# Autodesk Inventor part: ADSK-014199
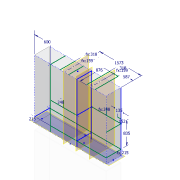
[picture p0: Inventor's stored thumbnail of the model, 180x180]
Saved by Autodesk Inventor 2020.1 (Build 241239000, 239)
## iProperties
Created: 2019-10
Part Number: ADSK-014199
Material: 1.0501 C35
Document SubType Name: Modeling
Designer: lutzd
Mass: 2.62307e+07 g
Surface Area: 174655 cm^2
Volume: 3.34575e+06 cm^3
Density: 7.84 g/cm^3
Appearance: Klar
VLDS_Profile: Default Part
VLDS_TimeStamp: 2016-07-29
VLDS_FailCnt: 0
VLDS_AcceptCnt: 0
Dimensions: 2690x559x2225 mm
Mass: 26230,717 kg
DocNumber: ADSK-014199
Folder: .
VDS_Category: 3D Komponenten
VDS_NumSchm: Autodesk
Title: skeleton
Author: lutzd
Revision Number: -
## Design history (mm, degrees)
sketch "Skizze1"
  geometry: L1 (-1345, -279.5)-(1345, -279.5); L2 (1345, -279.5)-(1345, 279.5); L3 (1345, 279.5)-(-1345, 279.5); L4 (-1345, 279.5)-(-1345, -279.5); L5 (-1345, -279.5)-(1345, 279.5); L6 (1345, -279.5)-(-1345, 279.5); 1 further point
  constraints: 12 end point, 2 midpoint, 2 parallel, 1 horizontal, 1 perpendicular
  dimensions: "d0" = 2690 distance of L2.end L3.end; "d1" = 559 distance of L1.end L2.end
extrude "Extrusion1" new body sketch "Skizze1" distance "d2" = 2225; taper "d3" = 0 deg
sketch "Skizze3"
  geometry: L1 (0, 2225)-(2690, 2225) reference; L2 (0, 0)-(0, 2225) reference; L3 (0, 0)-(2690, 0) reference; L4 (600, 2225)-(600, 0); L5 (2690, 0)-(2690, 2225) reference; L6 (600, 215)-(2690, 215); 1 further point
  constraints: 4 end point, 4 point on line, 2 perpendicular
  dimensions: "d5" = 600 distance between parallel lines of L2 L4; "d9" = 215 distance between parallel lines of L3 L6
sketch "Skizze5"
  geometry: L1 (0, 559)-(-2225, 559) reference; L2 (0, 0)-(0, 559) reference; L3 (0, 0)-(-2225, 0) reference; L4 (-215, 0)-(-215, 559); L5 (-1050, 0)-(-1050, 559); 1 further point
  constraints: 4 end point, 4 point on line, 1 perpendicular, 1 vertical
  dimensions: "d7" = 215 distance between parallel lines of L2 L4 (= d9); "d8" = 835 distance between parallel lines of L4 L5
workplane "Arbeitsebene1"
sketch "Skizze4"
  geometry: L1 (0, 0)-(-2225, 0) reference; L2 (-2225, 0)-(-2225, 559) reference; L3 (-215, 0)-(-215, 559) reference; L4 (0, 559)-(-2225, 559) reference; L5 (-1050, 0)-(-1050, 559) reference; 1 further point
sketch "Skizze6"
  geometry: L1 (215, 0)-(215, 559) reference; 1 further point
sketch "Skizze8"
  geometry: L1 (2690, -215)-(0, -215); 1 further point
  constraints: 2 end point, 1 horizontal
sketch "Skizze9"
  geometry: L1 (1345, 279.5)-(-1345, 279.5) reference; L2 (917, 820.5)-(917, -279.5); L3 (599, 820.5)-(599, -279.5); L4 (1345, -279.5)-(1345, 279.5) reference; L5 (-745, -279.5)-(-745, 279.5); L6 (-387, 279.5)-(-387, -279.5); L7 (-69, 279.5)-(-69, -279.5); L8 (758, 279.5)-(758, -279.5); L9 (-228, 279.5)-(-228, -279.5); L10 (917, 820.5)-(599, 820.5); 2 further points; 1 other entity
  constraints: 16 end point, 6 vertical, 5 point on line, 1 horizontal, 1 horizontal alignment, 1 parallel, 7 other
  dimensions: "d16" = 1100 distance of L3.start L3.end; "d19" = 587 distance between parallel lines of L4 L8; "d20" = 318 distance between parallel lines of L2 L3; "d21" = 159 distance between parallel lines of L2 L8 (= 0.5 x d20); "d23" = 1573 distance between parallel lines of L4 L9; "d24" = 318 distance between parallel lines of L6 L7 (= d20); "d25" = 159 distance between parallel lines of L7 L9 (= d21)
sketch "Skizze10"
  geometry: L1 (1585, 1050)-(600, 1050); L2 (1092.5, 1050)-(1092.5, 1298); 2 further points
  constraints: 4 end point, 1 horizontal, 1 midpoint, 1 vertical, 1 vertical alignment
  dimensions: "d27" = 248 distance of L2.start L2.end
sketch "Skizze11"
  geometry: L1 (2690, -1050)-(1585, -1050); L2 (2690, -1202)-(2555, -1202); L3 (2690, 0)-(2690, -2225) reference; L4 (2137.5, -1050)-(2137.5, -1298); 5 further points
  constraints: 6 end point, 2 horizontal, 1 midpoint, 1 point on line, 1 vertical
  dimensions: "d28" = 135 distance of L2.start L2.end; "d29" = 152 distance between parallel lines of L2 L1; "d30" = 248 distance of L4.start L4.end (= d27)
workplane "Arbeitsebene2"
workplane "Arbeitsebene3"
workplane "Arbeitsebene4"
node "Volumenkörper1"
other parameters: "d6" = -1105, "d15" = -35
